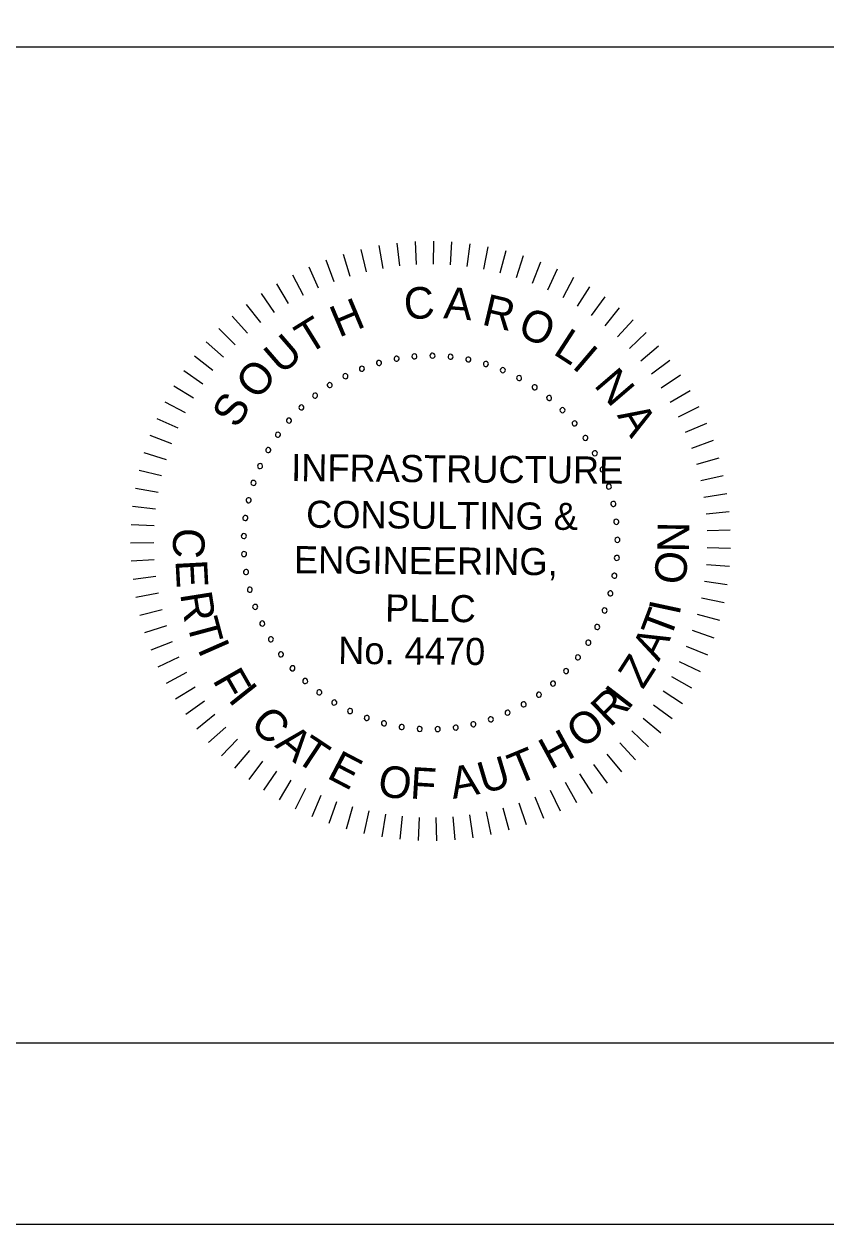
# Model space of a CAD drawing. Extents: x -225.1 to -152.9, y -16.8 to 27.2.
# Drawn here: x -174.66 to -170.23, y -16.78 to -10.15 of the extents above; entities that cross this region are included whole.
import ezdxf

# ---------------------------------------------------------------- set-up
doc = ezdxf.new("R2010")
doc.units = 0
for name, color, linetype in [('BR_BORDER LINES', 7, 'Continuous'), ('BR_TEXT', 7, 'Continuous'), ('Level 31', 7, 'Continuous')]:
    doc.layers.add(name, color=color, linetype=linetype)

msp = doc.modelspace()

# ---------------------------------------------------------------- linework, layer by layer
at = {"layer": 'BR_BORDER LINES'}
for p, q in [((-179.8094, -10.276), (-169.079, -10.276)), ((-221.4105, -15.7762), (-154.0784, -15.7762))]:
    msp.add_line(p, q, dxfattribs=at)
at = {"layer": 'BR_TEXT'}
for p, q in [((-172.7965, -11.3946), (-172.7668, -11.5184)), ((-172.6977, -11.3741), (-172.6755, -11.4995)), ((-172.5977, -11.3598), (-172.5833, -11.4863)), ((-172.4971, -11.3515), (-172.4904, -11.4786)), ((-172.3962, -11.3494), (-172.3972, -11.4767)), ((-172.2953, -11.3534), (-172.3041, -11.4804)), ((-172.1948, -11.3636), (-172.2114, -11.4898)), ((-172.0952, -11.3799), (-172.1194, -11.5049)), ((-172.9896, -11.4534), (-172.945, -11.5727)), ((-172.894, -11.4211), (-172.8568, -11.5428)), ((-171.9967, -11.4022), (-172.0285, -11.5255)), ((-171.8998, -11.4305), (-171.939, -11.5516)), ((-173.0831, -11.4915), (-173.0314, -11.6078)), ((-171.8048, -11.4646), (-171.8513, -11.5831)), ((-171.712, -11.5045), (-171.7657, -11.62)), ((-173.2623, -11.5844), (-173.1968, -11.6936)), ((-173.1741, -11.5352), (-173.1154, -11.6482)), ((-171.6219, -11.55), (-171.6825, -11.6619)), ((-173.3473, -11.6389), (-173.2752, -11.7439)), ((-171.5346, -11.6008), (-171.602, -11.7089)), ((-171.4507, -11.6569), (-171.5245, -11.7607)), ((-173.4288, -11.6985), (-173.3505, -11.7989)), ((-171.3703, -11.718), (-171.4503, -11.8171)), ((-173.5066, -11.7629), (-173.4222, -11.8583)), ((-171.2938, -11.7839), (-171.3797, -11.8779)), ((-173.5802, -11.832), (-173.4902, -11.9221)), ((-171.2215, -11.8543), (-171.3129, -11.9429)), ((-173.6496, -11.9054), (-173.5542, -11.9898)), ((-173.7143, -11.9829), (-173.614, -12.0614)), ((-171.1535, -11.9291), (-171.2502, -12.0119)), ((-171.0903, -12.0078), (-171.1919, -12.0846)), ((-173.7741, -12.0642), (-173.6693, -12.1364)), ((-171.032, -12.0902), (-171.138, -12.1607)), ((-173.8289, -12.149), (-173.7199, -12.2147)), ((-170.9788, -12.176), (-171.089, -12.2399)), ((-173.8785, -12.237), (-173.7656, -12.2959)), ((-170.9309, -12.2649), (-171.0448, -12.322)), ((-173.9226, -12.3278), (-173.8063, -12.3797)), ((-170.8886, -12.3566), (-171.0057, -12.4066)), ((-173.961, -12.4212), (-173.8418, -12.4659)), ((-170.8519, -12.4506), (-170.9719, -12.4934)), ((-173.9937, -12.5167), (-173.872, -12.5541)), ((-170.821, -12.5468), (-170.9434, -12.5821)), ((-174.0205, -12.614), (-173.8967, -12.6439)), ((-170.7961, -12.6446), (-170.9203, -12.6725)), ((-174.0413, -12.7128), (-173.916, -12.7351)), ((-170.7771, -12.7438), (-170.9029, -12.764)), ((-174.0561, -12.8127), (-173.9296, -12.8273)), ((-170.7643, -12.8439), (-170.891, -12.8564)), ((-174.0647, -12.9133), (-173.9376, -12.9202)), ((-170.7575, -12.9447), (-170.8848, -12.9494)), ((-174.0672, -13.0143), (-173.9399, -13.0134)), ((-170.7569, -13.0456), (-170.8843, -13.0426)), ((-174.0636, -13.1152), (-173.9365, -13.1065)), ((-170.7625, -13.1464), (-170.8894, -13.1357)), ((-174.0538, -13.2156), (-173.9275, -13.1993)), ((-170.7742, -13.2467), (-170.9002, -13.2283)), ((-174.0379, -13.3154), (-173.9128, -13.2913)), ((-174.0159, -13.4139), (-173.8925, -13.3823)), ((-170.792, -13.3461), (-170.9167, -13.32)), ((-170.8159, -13.4442), (-170.9387, -13.4106)), ((-173.988, -13.5109), (-173.8668, -13.4718)), ((-170.8456, -13.5407), (-170.9662, -13.4996)), ((-173.9542, -13.6061), (-173.8356, -13.5597)), ((-173.9146, -13.699), (-173.7991, -13.6454)), ((-170.8812, -13.6352), (-170.999, -13.5868)), ((-170.9225, -13.7273), (-171.0371, -13.6719)), ((-173.8695, -13.7893), (-173.7575, -13.7288)), ((-170.9693, -13.8168), (-171.0804, -13.7545)), ((-173.819, -13.8767), (-173.7108, -13.8095)), ((-171.0215, -13.9032), (-171.1285, -13.8342)), ((-173.7632, -13.9609), (-173.6593, -13.8872)), ((-171.0789, -13.9863), (-171.1815, -13.9109)), ((-173.7024, -14.0415), (-173.6032, -13.9616)), ((-173.6368, -14.1182), (-173.5427, -14.0325)), ((-171.1412, -14.0658), (-171.239, -13.9843)), ((-173.5666, -14.1908), (-173.4779, -14.0995)), ((-171.2083, -14.1412), (-171.3009, -14.0539)), ((-173.4922, -14.259), (-173.4092, -14.1624)), ((-171.2798, -14.2125), (-171.367, -14.1197)), ((-173.4137, -14.3225), (-173.3367, -14.2211)), ((-171.4352, -14.3413), (-171.5104, -14.2386)), ((-171.3555, -14.2793), (-171.4369, -14.1813)), ((-173.3315, -14.3812), (-173.2609, -14.2752)), ((-171.5185, -14.3984), (-171.5873, -14.2912)), ((-173.2459, -14.4347), (-173.1818, -14.3246)), ((-173.1571, -14.4829), (-173.0999, -14.3691)), ((-171.6051, -14.4502), (-171.6673, -14.3391)), ((-173.0656, -14.5255), (-173.0155, -14.4085)), ((-172.9717, -14.5626), (-172.9288, -14.4427)), ((-171.787, -14.5377), (-171.8352, -14.4198)), ((-171.6947, -14.4967), (-171.75, -14.382)), ((-172.8757, -14.5938), (-172.8401, -14.4715)), ((-172.7779, -14.6191), (-172.7499, -14.4949)), ((-172.0764, -14.6258), (-172.1024, -14.5011)), ((-171.9782, -14.6023), (-172.0117, -14.4795)), ((-171.8816, -14.5729), (-171.9226, -14.4523)), ((-172.6788, -14.6384), (-172.6584, -14.5127)), ((-172.5787, -14.6517), (-172.5661, -14.525)), ((-172.478, -14.6588), (-172.4731, -14.5315)), ((-172.3771, -14.6597), (-172.3799, -14.5324)), ((-172.2762, -14.6545), (-172.2868, -14.5276)), ((-172.1759, -14.6432), (-172.1942, -14.5172))]:
    msp.add_line(p, q, dxfattribs=at)
for centre, start, end in [((-172.5994, -11.9989), 10.60376, 190.60376), ((-172.5006, -11.9855), 5.06529, 185.06529), ((-172.5006, -11.9855), 185.06529, 5.06529), ((-172.401, -11.9817), 359.52683, 179.52683), ((-172.401, -11.9817), 179.52683, 359.52683), ((-172.3015, -11.9875), 173.98837, 353.98837), ((-172.3015, -11.9875), 353.98837, 173.98837), ((-172.2031, -12.0029), 348.44991, 168.44991), ((-172.7907, -12.0538), 21.68068, 201.68068), ((-172.7907, -12.0538), 201.68068, 21.68068), ((-172.6964, -12.0217), 16.14222, 196.14222), ((-172.6964, -12.0217), 196.14222, 16.14222), ((-172.5994, -11.9989), 190.60376, 10.60376), ((-172.2031, -12.0029), 168.44991, 348.44991), ((-172.1066, -12.0278), 162.91145, 342.91145), ((-172.1066, -12.0278), 342.91145, 162.91145), ((-172.0129, -12.0618), 157.37299, 337.37299), ((-172.0129, -12.0618), 337.37299, 157.37299), ((-172.8815, -12.0949), 27.21914, 207.21914), ((-172.8815, -12.0949), 207.21914, 27.21914), ((-171.9229, -12.1047), 151.83453, 331.83453), ((-171.9229, -12.1047), 331.83453, 151.83453), ((-173.0492, -12.2023), 38.29606, 218.29606), ((-172.9679, -12.1445), 32.7576, 212.7576), ((-172.9679, -12.1445), 212.7576, 32.7576), ((-171.8376, -12.1561), 146.29606, 326.29606), ((-171.8376, -12.1561), 326.29606, 146.29606), ((-173.1244, -12.2676), 43.83453, 223.83453), ((-173.0492, -12.2023), 218.29606, 38.29606), ((-171.7575, -12.2155), 140.7576, 320.7576), ((-171.7575, -12.2155), 320.7576, 140.7576), ((-173.1244, -12.2676), 223.83453, 43.83453), ((-171.6836, -12.2824), 135.21914, 315.21914), ((-171.6836, -12.2824), 315.21914, 135.21914), ((-173.1931, -12.3399), 49.37299, 229.37299), ((-173.1931, -12.3399), 229.37299, 49.37299), ((-171.6165, -12.356), 129.68068, 309.68068), ((-171.6165, -12.356), 309.68068, 129.68068), ((-173.2544, -12.4184), 54.91145, 234.91145), ((-173.2544, -12.4184), 234.91145, 54.91145), ((-171.5568, -12.4358), 124.14222, 304.14222), ((-171.5568, -12.4358), 304.14222, 124.14222), ((-173.3078, -12.5026), 60.44991, 240.44991), ((-173.3078, -12.5026), 240.44991, 60.44991), ((-171.5051, -12.521), 118.60376, 298.60376), ((-171.5051, -12.521), 298.60376, 118.60376), ((-173.3529, -12.5914), 65.98837, 245.98837), ((-173.3529, -12.5914), 245.98837, 65.98837), ((-171.4618, -12.6108), 113.06529, 293.06529), ((-171.4618, -12.6108), 293.06529, 113.06529), ((-173.3892, -12.6843), 71.52683, 251.52683), ((-173.3892, -12.6843), 251.52683, 71.52683), ((-171.4274, -12.7044), 107.52683, 287.52683), ((-171.4274, -12.7044), 287.52683, 107.52683), ((-173.4164, -12.7802), 77.06529, 257.06529), ((-173.4164, -12.7802), 257.06529, 77.06529), ((-171.4023, -12.8008), 101.98837, 281.98837), ((-171.4023, -12.8008), 281.98837, 101.98837), ((-173.4341, -12.8782), 82.60376, 262.60376), ((-173.4341, -12.8782), 262.60376, 82.60376), ((-171.3865, -12.8992), 96.44991, 276.44991), ((-171.3865, -12.8992), 276.44991, 96.44991), ((-173.4424, -12.9775), 88.14222, 268.14222), ((-173.4424, -12.9775), 268.14222, 88.14222), ((-171.3803, -12.9987), 90.91145, 270.91145), ((-171.3803, -12.9987), 270.91145, 90.91145), ((-173.441, -13.0772), 93.68068, 273.68068), ((-173.441, -13.0772), 273.68068, 93.68068), ((-171.3837, -13.0983), 85.37299, 265.37299), ((-171.3837, -13.0983), 265.37299, 85.37299), ((-173.43, -13.1762), 99.21914, 279.21914), ((-173.43, -13.1762), 279.21914, 99.21914), ((-171.3967, -13.1971), 79.83453, 259.83453), ((-171.3967, -13.1971), 259.83453, 79.83453), ((-173.4095, -13.2738), 104.7576, 284.7576), ((-173.4095, -13.2738), 284.7576, 104.7576), ((-171.4192, -13.2942), 74.29606, 254.29606), ((-171.4192, -13.2942), 254.29606, 74.29606), ((-173.3797, -13.3689), 110.29606, 290.29606), ((-173.3797, -13.3689), 290.29606, 110.29606), ((-171.451, -13.3886), 68.7576, 248.7576), ((-171.451, -13.3886), 248.7576, 68.7576), ((-173.3408, -13.4606), 115.83453, 295.83453), ((-173.3408, -13.4606), 295.83453, 115.83453), ((-171.4917, -13.4796), 63.21914, 243.21914), ((-171.4917, -13.4796), 243.21914, 63.21914), ((-173.2933, -13.5482), 121.37299, 301.37299), ((-173.2933, -13.5482), 301.37299, 121.37299), ((-171.5411, -13.5662), 57.68068, 237.68068), ((-171.5411, -13.5662), 237.68068, 57.68068), ((-173.2375, -13.6308), 126.91145, 306.91145), ((-173.2375, -13.6308), 306.91145, 126.91145), ((-171.5985, -13.6476), 52.14222, 232.14222), ((-171.5985, -13.6476), 232.14222, 52.14222), ((-173.174, -13.7076), 132.44991, 312.44991), ((-173.174, -13.7076), 312.44991, 132.44991), ((-171.6636, -13.7231), 46.60376, 226.60376), ((-171.6636, -13.7231), 226.60376, 46.60376), ((-173.1034, -13.778), 137.98837, 317.98837), ((-173.1034, -13.778), 317.98837, 137.98837), ((-171.7356, -13.792), 41.06529, 221.06529), ((-173.0263, -13.8412), 143.52683, 323.52683), ((-173.0263, -13.8412), 323.52683, 143.52683), ((-171.8139, -13.8536), 35.52683, 215.52683), ((-171.8139, -13.8536), 215.52683, 35.52683), ((-171.7356, -13.792), 221.06529, 41.06529), ((-172.9435, -13.8967), 149.06529, 329.06529), ((-172.9435, -13.8967), 329.06529, 149.06529), ((-171.8978, -13.9074), 29.98837, 209.98837), ((-171.8978, -13.9074), 209.98837, 29.98837), ((-172.8558, -13.9439), 154.60376, 334.60376), ((-172.8558, -13.9439), 334.60376, 154.60376), ((-172.7639, -13.9824), 160.14222, 340.14222), ((-172.7639, -13.9824), 340.14222, 160.14222), ((-172.0792, -13.9894), 18.91145, 198.91145), ((-171.9866, -13.9528), 24.44991, 204.44991), ((-171.9866, -13.9528), 204.44991, 24.44991), ((-172.6687, -14.0119), 165.68068, 345.68068), ((-172.6687, -14.0119), 345.68068, 165.68068), ((-172.5711, -14.032), 171.21914, 351.21914), ((-172.5711, -14.032), 351.21914, 171.21914), ((-172.472, -14.0427), 356.7576, 176.7576), ((-172.472, -14.0427), 176.7576, 356.7576), ((-172.3723, -14.0437), 2.29606, 182.29606), ((-172.3723, -14.0437), 182.29606, 2.29606), ((-172.273, -14.0351), 7.83453, 187.83453), ((-172.273, -14.0351), 187.83453, 7.83453), ((-172.175, -14.0169), 13.37299, 193.37299), ((-172.175, -14.0169), 193.37299, 13.37299), ((-172.0792, -13.9894), 198.91145, 18.91145)]:
    msp.add_arc(centre, 0.014, start, end, dxfattribs=at)
at = {"layer": 'Level 31'}
msp.add_lwpolyline([(-225.0771, -16.7761), (-153.0772, -16.7761), (-153.0772, 27.2239), (-225.0771, 27.2239)], close=True, dxfattribs=at)

# ---------------------------------------------------------------- texts
at = {"layer": 'BR_TEXT'}
for s, height, rotation, p in [('C', 0.1744, 4.72812, (-172.552, -11.7845)), ('A', 0.1744, 355.69809, (-172.3431, -11.7747)), ('R', 0.1744, 346.66807, (-172.1345, -11.8086)), ('H', 0.1744, 22.78817, (-172.9177, -11.8834)), ('O', 0.1744, 337.63804, (-171.9391, -11.8682)), ('T', 0.1744, 31.81819, (-173.0874, -11.9787)), ('L', 0.1744, 327.10802, (-171.7414, -11.9691)), ('U', 0.1744, 40.84822, (-173.234, -12.0909)), ('I', 0.1744, 319.578, (-171.6363, -12.0448)), ('O', 0.1744, 49.87824, (-173.368, -12.2329)), ('N', 0.1744, 310.54797, (-171.5146, -12.1463)), ('S', 0.1744, 58.90827, (-173.4788, -12.3893)), ('A', 0.1744, 301.51795, (-171.3845, -12.3112)), ('INFRASTRUCTURE', 0.149543, 359.52683, (-173.1816, -12.6743)), ('CONSULTING &', 0.149543, 359.52683, (-173.099, -12.9316)), ('N', 0.1744, 89.20849, (-170.9859, -13.0686)), ('C', 0.1744, 267.02504, (-173.8288, -12.9291)), ('ENGINEERING,', 0.149543, 359.52683, (-173.1662, -13.1824)), ('O', 0.1744, 83.20849, (-171.0081, -13.2515)), ('E', 0.1744, 273.02504, (-173.82, -13.1123)), ('R', 0.1744, 279.02504, (-173.7945, -13.2968)), ('PLLC', 0.14954, 359.52683, (-172.6628, -13.4496)), ('T', 0.1744, 69.39539, (-171.0905, -13.5551)), ('I', 0.1744, 77.90926, (-171.0391, -13.4202)), ('T', 0.1744, 285.02504, (-173.7597, -13.4544)), ('I', 0.1744, 293.77127, (-173.7003, -13.6006)), ('No. 4470', 0.14954, 359.52683, (-172.9219, -13.6833)), ('A', 0.1744, 63.39539, (-171.1521, -13.6758)), ('Z', 0.1744, 57.39539, (-171.2397, -13.8285)), ('F', 0.1744, 299.77127, (-173.6179, -13.7727)), ('I', 0.1744, 308.52683, (-173.5337, -13.8804)), ('R', 0.1744, 44.52683, (-171.4207, -14.0384)), ('I', 0.1744, 52.33388, (-171.3219, -13.9438)), ('C', 0.1744, 314.52683, (-173.415, -14.0207)), ('O', 0.1744, 38.52683, (-171.5738, -14.1583)), ('A', 0.1744, 320.52683, (-173.2767, -14.1378)), ('H', 0.1744, 28.52683, (-171.75, -14.2703)), ('T', 0.1744, 326.52683, (-173.1677, -14.2148)), ('E', 0.1744, 332.52683, (-172.9906, -14.3104)), ('T', 0.1744, 22.52683, (-171.9364, -14.3539)), ('O', 0.1744, 350.52683, (-172.7104, -14.4081)), ('A', 0.1744, 10.52683, (-172.2877, -14.4296)), ('U', 0.1744, 16.52683, (-172.1199, -14.4026)), ('F', 0.1744, 356.52683, (-172.5275, -14.4264))]:
    msp.add_text(s, height=height, rotation=rotation, dxfattribs=at).set_placement(p)

doc.saveas('drawing.dxf')
